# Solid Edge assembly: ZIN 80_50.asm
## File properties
Title: Zylinder
Author: bmolnar
Template: iso metric assembly.asm
Last saved by: bmolnar
Revision: 17
Application: Solid Edge
Username: bmolnar
Dokumentum tartalom típus: 1
Document Number: ZIN 80/50
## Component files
Kit_1.par
Kit_2.par
Kolbenstange.par
Profilrohr.par
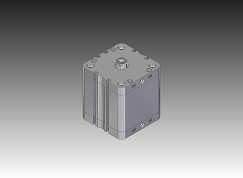
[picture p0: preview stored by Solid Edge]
